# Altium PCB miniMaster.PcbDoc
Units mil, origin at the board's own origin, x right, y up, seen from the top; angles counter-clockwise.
Board outline 1394 x 785 mil, 4 copper layers (Top Layer, GND, VCC, Bottom Layer); 65 components, 42 nets, 262 pads, 110 vias.
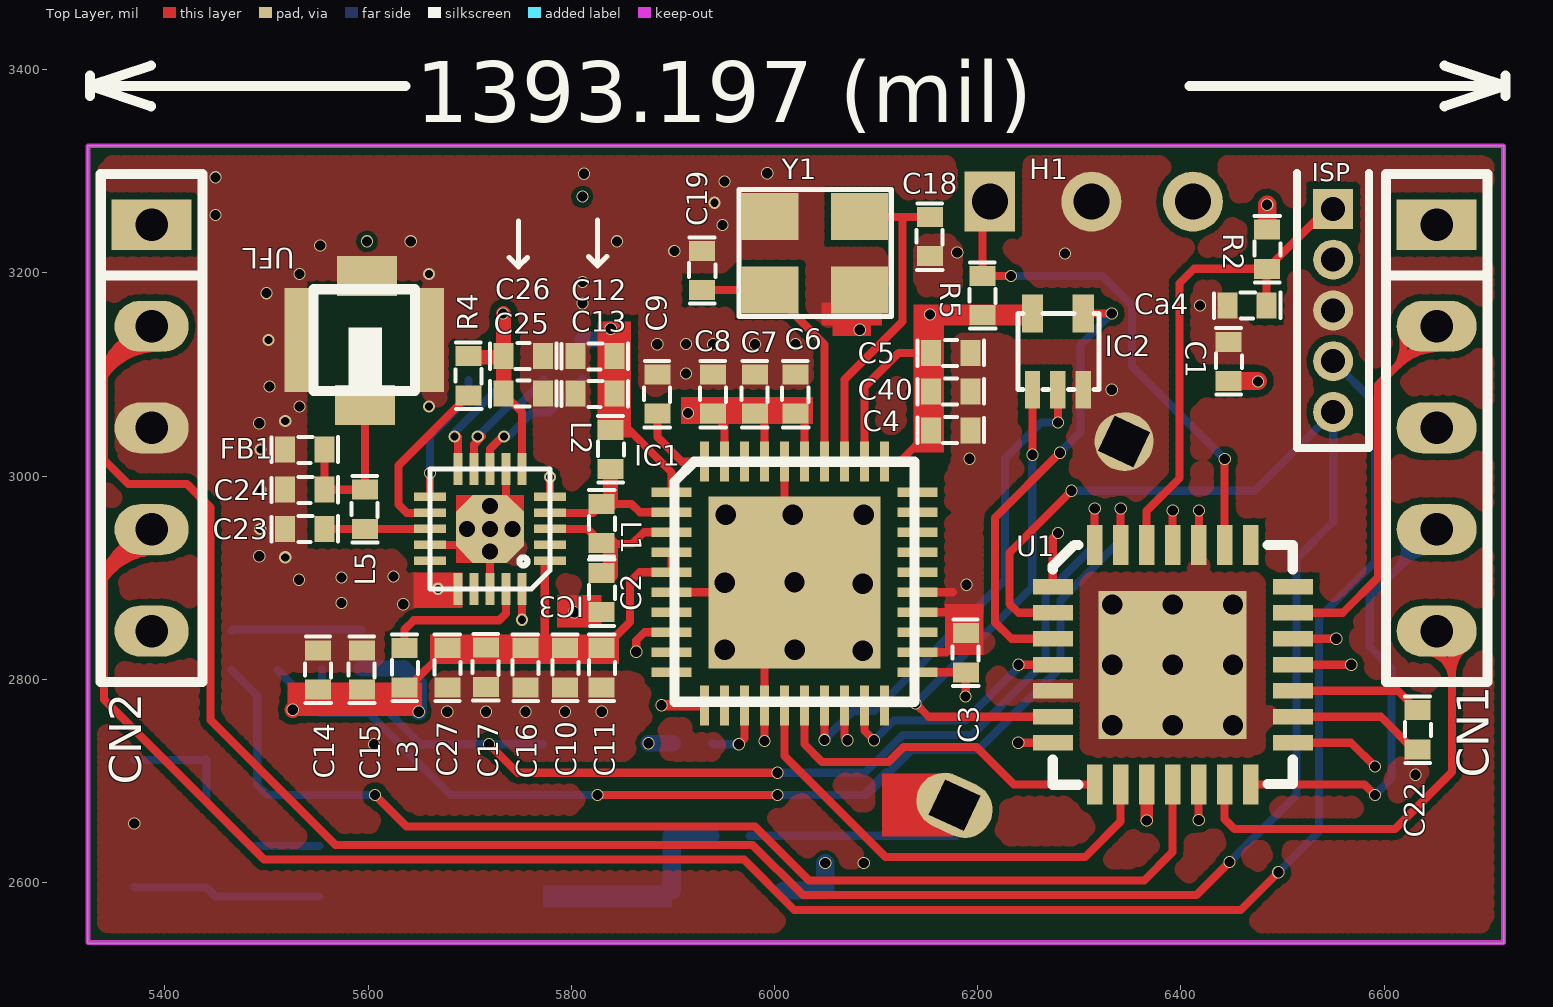
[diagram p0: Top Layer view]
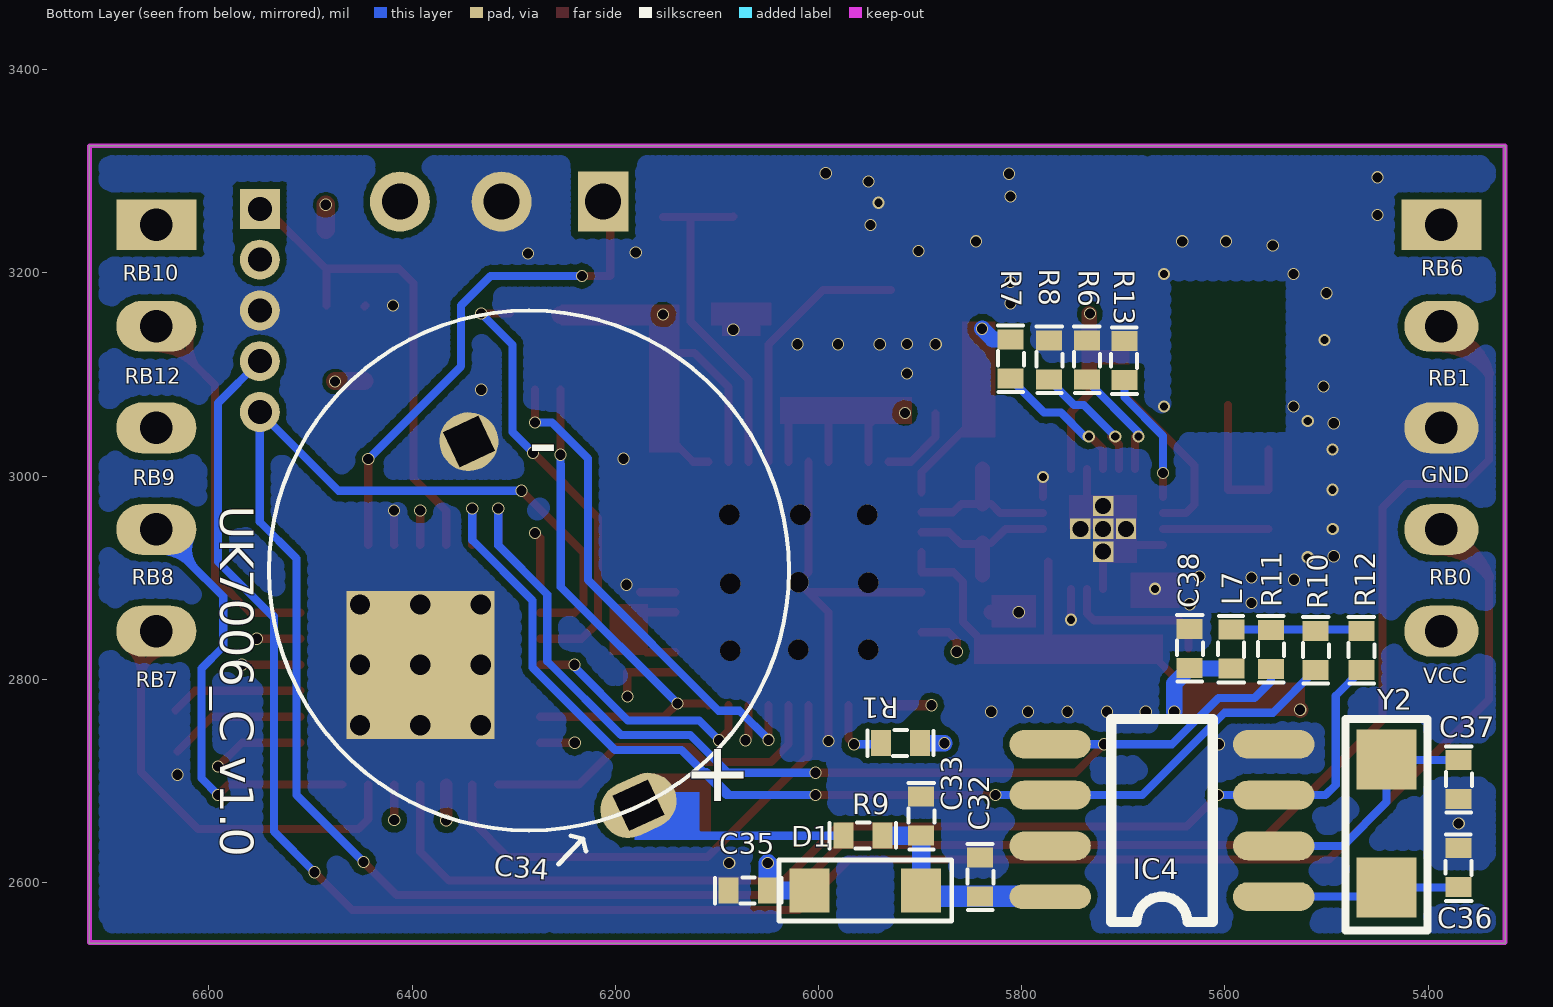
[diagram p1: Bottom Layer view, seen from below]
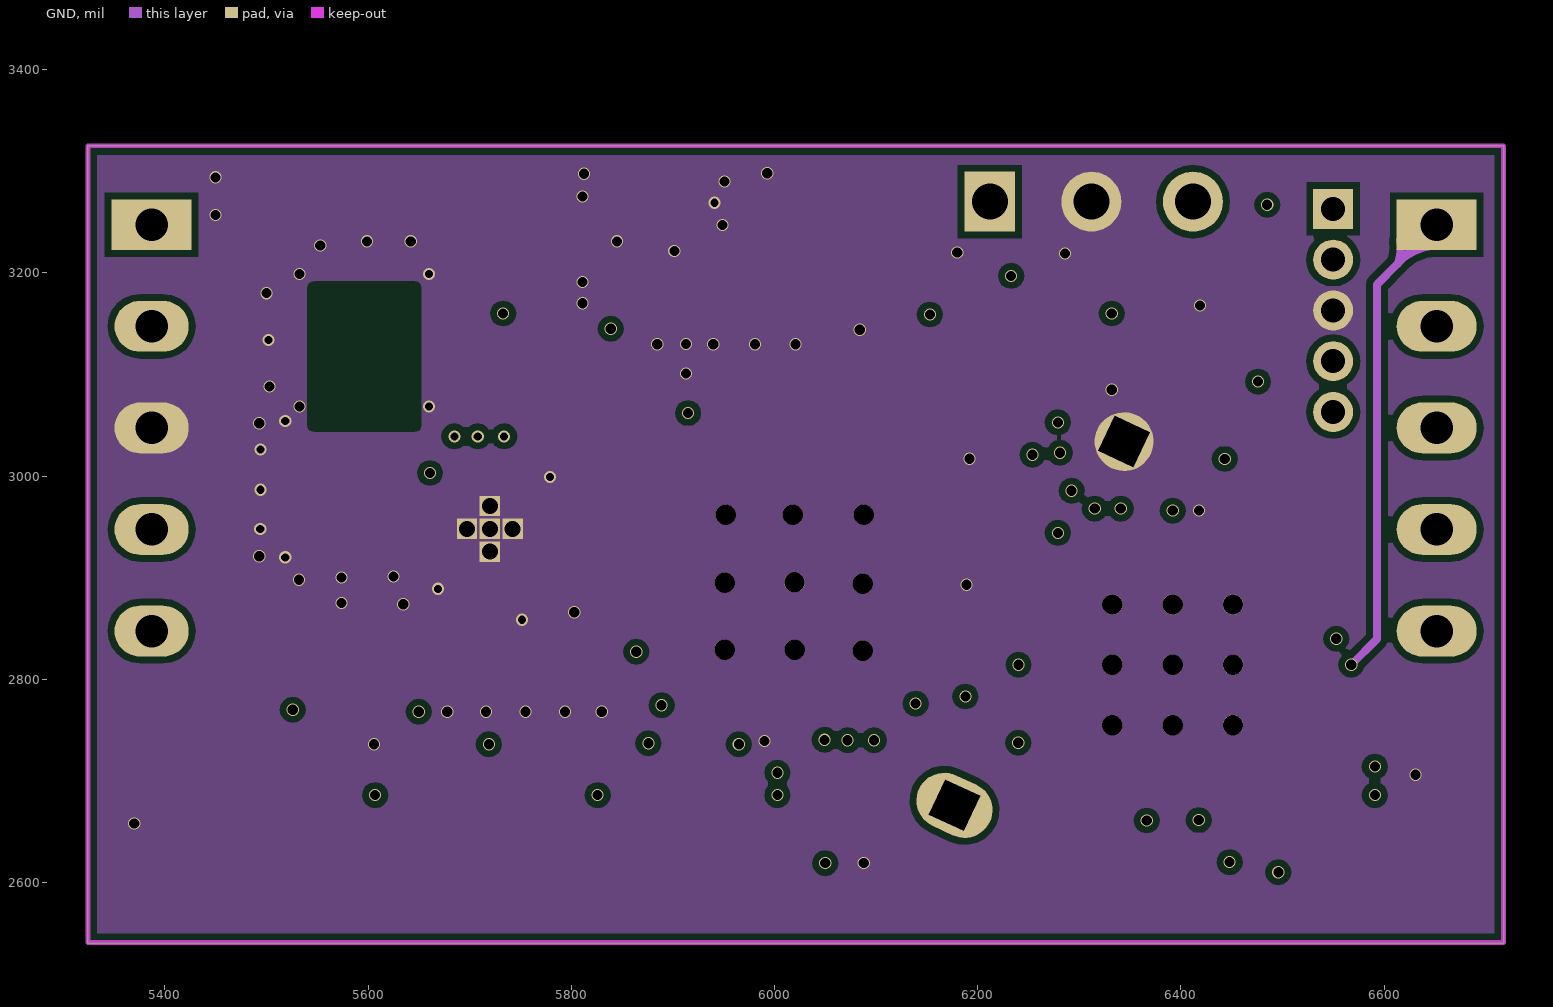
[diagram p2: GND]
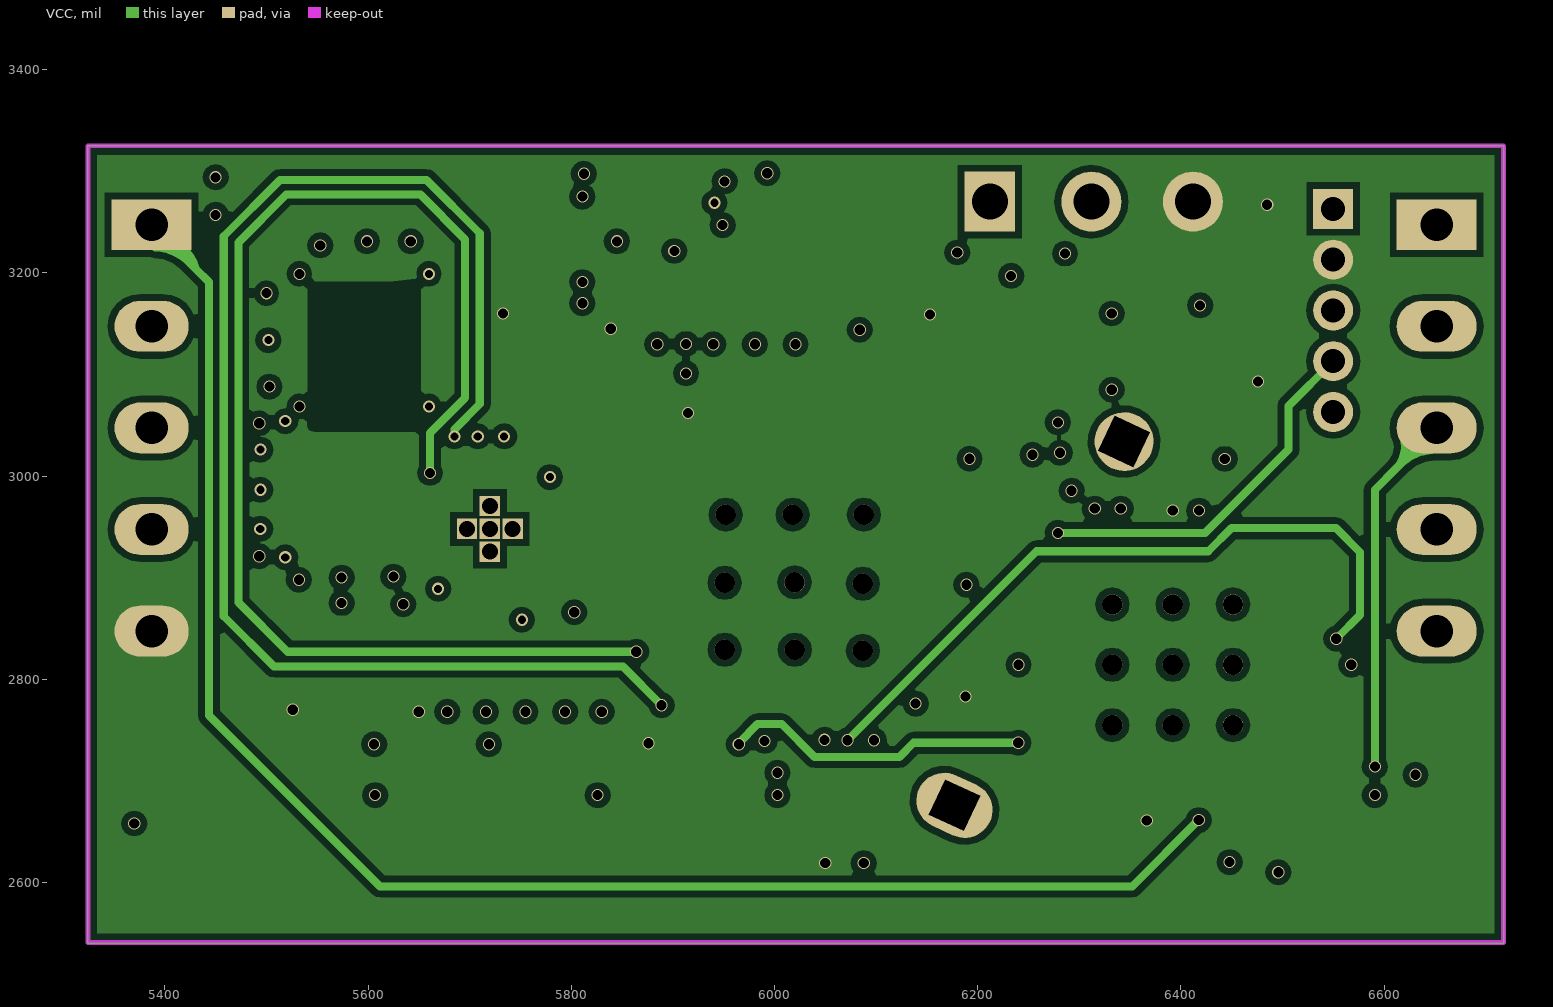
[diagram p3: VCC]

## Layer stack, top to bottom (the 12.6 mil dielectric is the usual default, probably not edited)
Top Layer: signal copper 1.4
Dielectric: core 12.6, FR-4, Dk 4.8
GND: signal copper 1.4
Dielectric: prepreg 12.6, FR-4, Dk 4.8
VCC: signal copper 1.4
Dielectric: core 12.6, FR-4, Dk 4.8
Bottom Layer: signal copper 1.4

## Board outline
5324,2540 5324,3325 6718,3325 6718,2540 5324,2540

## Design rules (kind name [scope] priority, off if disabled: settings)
Clearance [All] p1: gap=6.5
ComponentClearance [All] p1: gap=0 collisioncheckmode=3 verticalgap=0 showdistances=FALSE
HoleSize [All] p1: absolutevalues=TRUE maxlimit=1000 minlimit=1 maxpercent=80.000 minpercent=20.000
HoleToHoleClearance [All] p1: gap=0 allowstackedmicrovias=TRUE
MinimumSolderMaskSliver [All] p1: minsoldermaskwidth=0
PolygonConnect [All] p1: connectstyle=Direct reliefconductorwidth=10 reliefentries=4 polygonreliefangle="45 Angle"
RoutingVias [All] p1: holewidth=10 width=15 viastyle="Through Hole" minholewidth=8 minwidth=12 maxholewidth=18 maxwidth=100
SilkToSilkClearance [All] p1: silktosilkclearance=0
SilkscreenOverComponentPads [All] p1: minsilkscreentomaskgap=0
SolderMaskExpansion [All] p1: expansion=4
Width [All] p1: maxlimit=100 minlimit=8 preferedwidth=8
22 further rules are at their usual default settings.

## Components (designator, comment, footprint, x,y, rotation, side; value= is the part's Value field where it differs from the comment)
C1 "Cap" C0402 6447,3093.49 r90 top
C2 "Cap" C0402 5830,2866 r90 top
C3 "Cap" C0402 6188.35,2845.35 r270 top
C4 "Cap" C0402 6192.76,3045 r180 top
C5 "Cap" C0402 6192.76,3121 r180 top
C6 "Cap" C0402 6020.76,3100 r270 top
C7 "Cap" C0402 5980.76,3100 r270 top
C8 "Cap" C0402 5939.76,3100 r270 top
C9 "Cap" C0402 5884.76,3100 r270 top
C10 "Cap" C0402 5794,2792 r90 top
C11 "Cap" C0402 5830,2792 r90 top
C12 "Cap" C0402 5804,3118 r0 top
C13 "Cap" C0402 5804,3081 r0 top
C14 "Cap" C0402 5551,2828.51 r270 top
C15 "Cap" C0402 5594,2828.51 r270 top
C16 "Cap" C0402 5755,2792 r90 top
C17 "Cap" C0402 5716,2831 r270 top
C18 "Cap" C0402 6153,3255 r270 top
C19 "Cap" C0402 5928.76,3183 r90 top
C22 "Cap" C0402 6633,2731 r90 top
C23 "Cap" C0402 5518.49,2948.06 r0 top
C24 "Cap" C0402 5518.49,2986.57 r0 top
C25 "Cap" C0402 5772,3081 r180 top
C26 "Cap" C0402 5772,3118 r180 top
C27 "Cap" C0402 5678,2792 r90 top
C32 "Cap" C0402 5841,2586 r90 bottom
C33 "Cap" C0402 5899,2646 r90 bottom
C34 "Cap Pol1" 0.22f 6285,2907 r65 bottom
C35 "Cap" C0402 6050,2592 r0 bottom
C36 "Cap" C0402 5370,2634 r270 bottom
C37 "Cap" C0402 5370,2682 r90 bottom
C38 "Cap" C0402 5634.76,2811 r90 bottom
C40 "Cap" C0402 6192.76,3083 r180 top
Ca4 "Cap" C0402 6446,3168 r0 top
CN1 "CN1" SIP5#1 6651.87,3047.4 r270 top locked
CN2 "CN2" SIP5#2 5386.99,3047.4 r270 top locked
D1 "Diode 1N4148WS" sod323 6009,2592 r180 bottom
FB1 "Res1" C0402 5518.49,3026 r0 top
H1 "H1" HDR1X3 6212,3270 r0 top locked
IC1 "mrf24j40" mrf24j40 5898.76,2984 r0 top
IC2 "NC7SZ125P5X" NC7SZ125P5X 6254,3085 r0 top
IC3 "2438T" 2438T 5779,2889 r180 top locked
IC4 "pcf8563T" pcf8563t 5552,2586 r90 bottom
ISP "ISP" 1.27MM 6550,3263 r90 top locked
L1 "Inductor" c0402 5830,2934 r90 top
L2 "Inductor" c0402 5838.76,3007 r90 top
L3 "Inductor" c0402 5636,2792 r90 top
L5 "Inductor" c0402 5597,2986.57 r270 top
L7 "Inductor" c0402 5593.76,2849 r270 bottom
R1 "Res1" C0402 5900,2737 r0 bottom
R2 "Res1" C0402 6485,3204 r90 top
R4 "Res1" C0402 5699,3118 r270 top
R5 "Res2" C0402 6205,3197 r270 top
R6 "Res1" C0402 5736,3095 r90 bottom
R7 "Res1" C0402 5811,3096 r90 bottom
R8 "Res1" C0402 5773,3095 r90 bottom
R9 "Res1" C0402 5937,2646 r0 bottom
R10 "Res1" C0402 5510.76,2809 r90 bottom
R11 "Res1" C0402 5554.76,2810 r90 bottom
R12 "Res1" C0402 5465.76,2809 r90 bottom
R13 "Res1" C0402 5699,3133 r270 bottom
U1 "QFN256" QFN256 6274,2891 r0 top locked
UFL "IPEX" UFL 5597,3070 r270 top locked
Y1 "20MHz" 20mhz 5995.76,3183 r0 top
Y2 "32.768k" 32.768K 5441,2721 r270 bottom

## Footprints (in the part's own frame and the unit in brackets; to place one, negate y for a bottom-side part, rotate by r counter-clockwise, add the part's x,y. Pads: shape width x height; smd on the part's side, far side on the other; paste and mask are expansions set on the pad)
0.22f [mil]
  oval 55x77 hole 38 square: 1(-255,0)
  round 58 hole 38 square: 2(140,0)
  silkscreen extent -256,-256 256,256
1.27MM [mm]
  rect 1x1 hole 0.6: 1(0,0)
  round 1 hole 0.6: 2(-1.27,0) 3(-2.54,0) 4(-3.81,0) 5(-5.08,0)
  silkscreen extent -5.98,-0.9 0.9,0.9
20mhz [mil]
  rect 56x46 smd: 0(0,72.56) 0(88,0) 1(0,0) 2(88,72.56)
  silkscreen extent -31,-26 119,99
32.768K [mm]
  rect 1.5x1.5 smd: 1(0,0) 2(3.2,0)
  silkscreen extent -1.01,-1.02 4.27,1.03
2438T [mm]
  rect 0.508x0.508 hole 0.4: 0(0.93,-1.5) 0(1.5,-2.07) 0(1.5,-1.5) 0(1.5,-0.93) 0(2.07,-1.5)
  oct 1.7x1.7 smd: 0(1.5,-1.5)
  rect 0.8x0.22 smd: 1(0,-0.7) 2(0,-1.1) 3(0,-1.5) 4(0,-1.9) 5(0,-2.3) 11(3,-2.3) 12(3,-1.9) 13(3,-1.5) 14(3,-1.1) 15(3,-0.7)
  rect 0.22x0.8 smd: 6(0.7,-3) 7(1.1,-3) 8(1.5,-3) 9(1.9,-3) 10(2.3,-3) 16(2.3,0) 17(1.9,0) 18(1.5,0) 19(1.1,0) 20(0.7,0)
  Top Layer region: 1.5,-2.35 2.35,-2.35 2.35,-0.65 1.5,-0.65
  Top Layer region: 0.65,-2.35 2.35,-2.35 2.35,-1.5 0.65,-1.5
  silkscreen extent 0,-3 3,0
C0402 [mm]
  rect 0.5x0.65 smd: 1(0,0) 2(0.978,0)
  silkscreen extent -0.34,-0.33 1.32,0.32
c0402 [mm]
  rect 0.5x0.65 smd: 1(0,0) 2(0.978,0)
  silkscreen extent -0.34,-0.33 1.32,0.32
HDR1X3 [mm] "Connector; Header; 3 Position"
  rect 1.27x1.5 hole 0.9: 1(0,0)
  round 1.5 hole 0.9: 2(2.54,0) 3(5.08,0)
mrf24j40 [mm]
  rect 1x0.23 smd: 1(0,0) 2(0,-0.5) 3(0,-1) 4(0,-1.5) 5(0,-2) 6(0,-2.5) 7(0,-3) 8(0,-3.5) 9(0,-4) 10(0,-4.5) 21(6.15,-4.5) 22(6.15,-4) 23(6.15,-3.5) 24(6.15,-3) 25(6.15,-2.5) 26(6.15,-2) 27(6.15,-1.5) 28(6.15,-1) 29(6.15,-0.5) 30(6.15,0)
  round 0.508 hole 0.508: 10(1.327,-3.937) 10(1.327,-2.261) 10(1.352,-0.559) 10(3.029,-0.559) 10(3.075,-2.25) 10(3.079,-3.937) 10(4.781,-3.962) 10(4.781,-2.286) 10(4.807,-0.559)
  rect 0.23x1 smd: 11(0.825,-5.325) 12(1.325,-5.325) 13(1.825,-5.325) 14(2.325,-5.325) 15(2.825,-5.325) 16(3.325,-5.325) 17(3.825,-5.325) 18(4.325,-5.325) 19(4.825,-5.325) 20(5.325,-5.325) 31(5.325,0.765) 32(4.825,0.765) 33(4.325,0.765) 34(3.825,0.765) 35(3.325,0.765) 36(2.825,0.765) 37(2.325,0.765) 38(1.825,0.765) 39(1.325,0.765) 40(0.825,0.765)
  rect 4.3x4.3 smd: 41(3.075,-2.25)
  silkscreen extent 0.07,-5.24 6.07,0.76
NC7SZ125P5X [mil]
  rect 15x37 smd: 1(0,0) 2(25,0) 3(50,0)
  rect 21x37 smd: 4(50,75) 5(0,75)
  silkscreen extent -14,0 66,75
pcf8563t [mil]
  oval 28.35x80 smd: 1(0,0) 2(50,0) 3(100,0) 4(150,0) 5(150,220) 6(100,220) 7(50,220)
  oval 24x80 smd: 8(0,220)
  silkscreen extent -25,60 175,160
QFN256 [mm]
  rect 3.7x3.7 smd: 0(2.997,-1.95)
  rect 1x0.38 smd: 1(0,0) 2(0,-0.65) 3(0,-1.3) 4(0,-1.95) 5(0,-2.6) 6(0,-3.25) 7(0,-3.9) 15(6,-3.9) 16(6,-3.25) 17(6,-2.6) 18(6,-1.95) 19(6,-1.3) 20(6,-0.65) 21(6,0)
  rect 0.38x1 smd: 8(1.047,-4.947) 9(1.697,-4.947) 10(2.347,-4.947) 11(2.997,-4.947) 12(3.647,-4.947) 13(4.297,-4.947) 14(4.947,-4.947) 22(4.947,1.047) 23(4.297,1.047) 24(3.647,1.047) 25(2.997,1.047) 26(2.347,1.047) 27(1.697,1.047) 28(1.047,1.047)
  silkscreen extent 0,-4.95 6,1.05
SIP5#1 [mil]
  rect 50x78.74 hole 32: 1(-200,0)
  oval 50x78.74 hole 32: 2(-100,0) 3(0,0) 4(100,0) 5(200,0)
  silkscreen extent -250,-50 250,50
SIP5#2 [mil]
  rect 50x78.74 hole 32: 1(-200,0)
  oval 50x73 hole 32: 2(-100,0) 3(0,0) 4(100,0) 5(200,0)
  silkscreen extent -250,-50 250,50
sod323 [mm]
  rect 1x1.1 smd: 1(0,0) 2(2.794,0)
  silkscreen extent -0.76,-0.76 3.56,0.76
UFL [mm]
  rect 1x1.5 smd: 1(0,0) 3(-3.22,0.05)
  rect 2.6x0.75 smd: 2(-1.62,1.6) 4(-1.62,-1.64)
  silkscreen extent -2.89,-1.29 -0.35,1.25

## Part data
C1 C2 C3 C4 C5 C6 C7 C8 C9 C10 C11 C12 C13 C14 C15 C16 C17 C18 C19 C22 C23 C24 C25 C26 C27 C32 C33 C35 C36 C37 C38 C40 Ca4: "Capacitor"
C34: "Polarized Capacitor (Radial)"
CN1 CN2 ISP: library part CON5, "Connector"
D1: library part "Diode 1N4148", "High Conductance Fast Diode"
FB1 R1 R2 R4 R5 R6 R7 R8 R9 R10 R11 R12 R13: "Resistor"
H1: library part "Header 3", "Header, 3-Pin"
UFL: library part "Header 4", "Hea"
Y1 Y2: library part XTAL, "Crystal Oscillator"

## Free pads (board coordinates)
  rect 145.67x145.67 smd far side: 0(6392,2814.23)
  round 20 hole 20: 1(6332.64,2754.87) 1(6332.64,2814.23) 1(6332.64,2873.59) 1(6392,2754.87) 1(6392,2814.23) 1(6392,2873.59) 1(6451.36,2754.87) 1(6451.36,2814.23) 1(6451.36,2873.59)

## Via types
v1: diameter 12, hole 10, Top Layer to Bottom Layer, 95 vias
v2: diameter 12, hole 8, Top Layer to Bottom Layer, 15 vias

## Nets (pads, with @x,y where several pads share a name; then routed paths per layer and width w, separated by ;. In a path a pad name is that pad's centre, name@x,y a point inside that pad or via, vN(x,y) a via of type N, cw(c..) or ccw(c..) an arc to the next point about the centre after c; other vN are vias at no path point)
C\S\: IC1.20 IC2.1 U1.6 | length 648.7
  Top Layer w8: IC1.20 6110.06,2776 v1(6139,2776) 6151.95,2763.05 U1.6 ; v1(6254,3021) IC2.1
  Bottom Layer w8: v1(6139,2776) 6253.76,2890.76 ; 6253.76,3011.24 6253.76,2890.76 ; v1(6254,3021) 6254,2891 6253.76,2890.76
CPS: IC3.8 R7.1 | length 139.5
  Top Layer w8: IC3.8 5719.94,3026.44 5732.51,3039 v2(5734,3039)
  Bottom Layer w8: v2(5734,3039) 5737.99,3039 5761.5,3062.5 5777.99,3062.5 5811,3095.51 R7.1
CRX: IC1.11 IC3.10 R6.1 | length 1499.8
  Top Layer w8: v2@5688,3039 5688.45,3038.55 IC3.10
  Top Layer w10: v1(5889,2774.35) IC1.11
  VCC w8: v2(5685,3039) 5685,3046 5710,3071 5710,3239 5657.5,3291.5 5513.49,3291.5 5458,3236.01 5458,2862 5507.5,2812.5 5850.85,2812.5 v1(5889,2774.35)
  Bottom Layer w8: v2(5685,3039) 5685,3043 5736,3094 R6.1
CSD: IC3.12 R4.2 | length 170.4
  Top Layer w8: IC3.12 5638.2,2963.8 5630,2972 5630,3010.49 R4.2
CTX: IC1.8 IC3.11 R13.2 | length 1447
  Top Layer w8: IC3.11 5660.89,2998.89 v1@5661,2999 ; v1(5864,2827) 5864,2838 5872.2,2846.2 IC1.8
  VCC w8: v1(5661,3003) 5661,3042.51 5695.5,3077.01 5695.5,3232.99 5651.49,3277 5519.5,3277 5472.5,3230 5472.5,2875.5 5521,2827 v1(5864,2827)
  Bottom Layer w8: v1(5661,3003) 5661,3039.51 5699,3077.51 R13.2
GND: C1.2 C2.1 C3.1 C4.1 C5.1 C6.1 C7.1 C8.1 C9.1 C10.1 C11.1 C12.1 C13.1 C14.1 C15.1 C16.1 C17.2 C18.2 C19.2 C22.1 C23.1 C24.1 C25.1 C26.1 C27.1 C32.2 C33.2 C34.2 C35.2 C36.1 C37.1 C38.2 C40.1 Ca4.1 CN2.3 FB1.1 H1.2 IC1.6 IC1.10@5951,2829 IC1.10@5951,2895 IC1.10@5952,2962 IC1.10@6018,2962 IC1.10@6019.83,2895.42 IC1.10@6020,2829 IC1.10@6087,2828 IC1.10@6087,2894 IC1.10@6088,2962 IC1.14 IC1.22 IC1.24 IC1.25 IC1.36 IC1.41 IC2.3 IC3.0 IC3.5 IC3.7 IC3.14 IC3.16 IC3.18 IC3.20 IC4.4 ISP.3 pad.0 pad.1 R6.2 R8.2 R13.1 U1.0 U1.5 U1.16 U1.24 UFL.2 UFL.3 UFL.4 Y1.0 | length 1020
  Top Layer w8: IC3.14 5704.2,2932.31 IC3.0@5719.94,2948.06 ; v2(5669,2889) IC3.16 ; IC3.18 5719.94,2925.61 IC3.0@5719.94,2948.06 ; IC3.7 5735.69,2963.8 5731.17,2959.28 IC3.0@5719.94,2948.06 ; v2(5751.44,2858.56) IC3.20 ; IC3.5 v2(5779,2999) ; v1@5810.54,3274.54 v1(5811,3275) ; IC1.6 IC1.41@6009.98,2885.57 ; v1(5990.3,2739.3) IC1.14 5990.3,2865.89 IC1.41@6009.98,2885.57 ; IC1.36 6009.98,2905.26 IC1.41 IC1.41@6009.98,2885.57 ; IC1.22 6169.52,2826.52 C3.1 ; IC1.24 6174.92,2865.89 ; IC1.25 6175.6,2885.57 ; U1.0@6366.41,2788.64 U1.0 ; U1.24 6418,2932.64 v1(6418,2966) ; Ca4.1 Ca4.1@6447,3167 ; U1.16 6596.95,2763.05 C22.1@6631,2729
  Top Layer w15: v1(5803,2866) C2.1
  other v1: 6088,2619 5370,2658 6631,2706 5606,2736 5678,2768 5716,2768 5755,2768 5794,2768 5830,2768 5634.76,2873.76 5574,2875 6189,2893 5532,2898 5574,2900 5625,2901 5493,2921 6192,3017 5493,3052 5532.43,3068.57 6332,3085 5503,3088 5913,3101 5884.76,3129.76 5913,3130 5939.76,3129.76 5980.76,3129.76 6020.76,3129.76 6084,3144 6419,3168 5811,3170 5500,3180 5811,3191 5532.43,3198.99 6286,3219 6180,3220 5901.51,3221.51 5553,3227 5599,3231 5642,3231 5845,3231 5949,3247 5450,3257 5951,3290 5450,3294 5812.52,3297.57 5993,3298
  other v2: 5518.49,2920 5494,2948 5494.06,2986.57 5494.06,3026 5518.49,3054.06 5659.99,3068.57 5502,3133.78 5659.99,3198.99 5941,3269
INT: IC1.16 U1.8 | length 352.5
  Top Layer w8: IC1.16 6029.67,2736 6047,2718.67 6112.43,2718.67 6127,2733.23 6167.12,2733.23 6198.77,2733.23 6235.77,2696.23 U1.8
INT_T: IC4.3 R12.1 U1.11 | length 1141.2
  Top Layer w8: v1(5607,2686) 5638,2655 5981,2655 6034,2602 6364,2602 6392,2630 U1.11
  Bottom Layer w8: R12.1 5491,2783.76 5491,2696 5501,2686 IC4.3 v1(5607,2686)
ISPCLK: CN2.2 ISP.5 U1.2 | length 2636.4
  Top Layer w8: CN2.2 5339.99,3100.4 5339.99,3016.01 5364,2992 5422,2992 5445,2969 5445,2760 5568,2637 5978.49,2637 6027.99,2587.5 6415.5,2587.5 v1(6448,2620) ; U1.2 6240.09,2865.41 6231.5,2874 6231.5,2924.48 v1(6292.51,2985.49)
  Top Layer w10: CN2.2@5365.3,3135.53 ccw(c5397,3086) 5339.99,3100.4 cw(c5393,3061) CN2.2@5393.64,3127.05
  Bottom Layer w8: v1(6292.51,2985.49) 6472.49,2985.49 ISP.5 6550,2955 6514,2919 6514,2686 v1(6448,2620)
ISPDAT: CN2.4 ISP.4 U1.1 | length 2558.7
  Top Layer w8: CN2.4 5339.99,2900.4 5339.99,2780.01 5497.5,2622.5 5970,2622.5 6019.5,2573 6459,2573 v1(6496,2610) ; U1.1 6274,2939 v1(6279,2944)
  Top Layer w10: CN2.4@5387.94,2942.13 ccw(c5399,2881) 5339.99,2900.4 cw(c5393,2861) CN2.4@5394.74,2927.03
  VCC w8: v1(6279,2944) 6424,2944 6506,3026 6506,3069 ISP.4 ISP.4@6550,3109.67
  Bottom Layer w8: v1(6496,2610) 6536,2650 6536,2862 6537.33,2862 6591,2915.67 6591,3072 ISP.4
MCLR: Ca4.2 ISP.1 R2.1 U1.26 | length 488.7
  Top Layer w8: U1.26 6366.41,2965.41 6398.78,2997.78 6398.78,3189.78 6413,3204 R2.1 ; Ca4.2 6484.51,3203.51 R2.1 ; ISP.1 6544,3263 R2.1
NetC9_2: C9.2 IC1.40 | length 79.7
  Top Layer w8: C9.2 5884.76,3038.24 5908.88,3014.12 IC1.40
NetC18_1: C18.1 IC1.33 Y1.2 | length 333.9
  Top Layer w8: IC1.33 6069.04,3095.04 6126,3152 6126,3255 ; Y1.2 6084.33,3255 6126,3255 ; C18.1 6126,3255
NetC19_1: C19.1 IC1.34 Y1.1 | length 258.1
  Top Layer w8: C19.1 Y1.1 6049.35,3129.41 IC1.34
NetC22_2: C22.2 U1.17 | length 130.7
  Top Layer w8: U1.17 6613.87,2788.64 C22.2
NetC24_2: C24.2 FB1.2 L5.1 UFL.1 | length 162.9
  Top Layer w8: FB1.2 C24.2 L5.1 UFL.1
NetC32_1: C32.1 C33.1 D1.2 IC4.8 R9.1 | length 92
  Bottom Layer w18: D1.2 C33.1 R9.1
NetC34_1: C34.1 R9.2 | length 171.8
  Bottom Layer w8: R9.2 6117.34,2646 6138.5,2667.16
NetC36_2: C36.2 IC4.1 Y2.2 | length 185.9
  Bottom Layer w8: C36.2 5370.47,2595.02 Y2.2 5450.02,2586 IC4.1
NetC37_2: C37.2 IC4.2 Y2.1 | length 242
  Bottom Layer w8: C37.2 5440.51,2720.51 Y2.1 5441,2679 5484,2636 IC4.2
NetIC1_17: IC1.17 IC2.2 | length 495.7
  Top Layer w8: v1(6049.35,2740.36) IC1.17 ; v1(6279,3052.76) IC2.2
  Bottom Layer w8: v1(6049.35,2740.36) 6049.35,2740.69 6077.67,2769 6098.5,2769 6227,2897.5 6227,3017.33 6262.43,3052.76 v1(6279,3052.76)
NetIC3_9: IC3.9 R8.1 | length 123.6
  Top Layer w8: IC3.9 5704.2,3031.2 v2@5712,3039
  Bottom Layer w8: v2(5708,3039) 5739,3070 5748.49,3070 5773,3094.51 R8.1
NetIC3_19: IC3.19 L3.2 | length 149
  Top Layer w8: L3.2 5636,2849 5645,2858 5729,2858 5735.69,2864.69 IC3.19
NetL7_1: L7.1 R10.2 R11.2 R12.2 | length 128.6
  Bottom Layer w8: R12.2 5467.25,2849 L7.1
R\E\S\E\T\: IC1.13 R1.2 U1.7 | length 404.7
  Top Layer w8: v1(5965,2736) 5970.61,2741.61 IC1.13 ; v1(6240,2737.46) U1.7
  VCC w8: v1(5965,2736) 5965,2737.33 5983.47,2755.8 6007.2,2755.8 6039.5,2723.5 6123.04,2723.5 6137,2737.46 v1(6240,2737.46)
  Bottom Layer w8: R1.2 5939.51,2736 v1(5965,2736)
RB6: CN2.1 U1.12 | length 1686.1
  Top Layer w8: v1(6417.59,2661.41) U1.12
  VCC w8: CN2.1 5421,3213.39 ; CN2.1@5390.64,3225.18 cw(c5389,3176) 5421,3213.39 ; CN2.1@5403.88,3233.09 cw(c5388,3192) 5430.39,3204 ; v1(6417.59,2661.41) 6352.18,2596 5611.99,2596 5443.5,2764.49 5443.5,3190.89 5430.39,3204 ; 5421,3213.39 5430.39,3204
RB7: CN1.5 U1.13 | length 505.8
  Top Layer w8: U1.13 6443.18,2662.32 6453,2652.5 6610.64,2652.5 6667,2708.86 6667,2804 ; CN1.5@6637.86,2827.42 cw(c6639,2799) 6667,2804 ; CN1.5 6667,2832.27 6667,2808 ; CN1.5@6682.5,2833.49 ccw(c6699,2806) 6667,2808 ; 6667,2804 cw(c6699,2806) 6667,2808 ; 6667,2804 6667,2808
RB8: CN1.4 U1.14 | length 506
  Top Layer w8: U1.14 6580.77,2696.23 v1(6591,2686)
  Bottom Layer w8: v1(6591,2686) 6607.5,2702.5 6607.5,2810.5 6586,2832 6586,2881.53 6621,2916.53 ; CN1.4@6617.8,2940.51 cw(c6591,2928) 6614.47,2910 cw(c6650,2881) 6621,2916.53 ; CN1.4 6621,2916.53 ; CN1.4@6652.18,2926.81 ccw(c6650,2881) 6621,2916.53
RB9: CN1.3 U1.15 | length 526.9
  Top Layer w8: U1.15 6567.54,2737.46 v1(6591,2714)
  VCC w8: v1(6591,2714) 6591,2986.53 6612.47,3008 ; CN1.3@6616.89,3043.94 cw(c6590,3029) 6613.53,3009.19 ; CN1.3@6646.24,3025.82 ccw(c6652,2974) 6618,3013.53 ; CN1.3 6618,3013.53 ; 6612.47,3008 cw(c6652,2974) 6613.53,3009.19 ; 6612.47,3008 ccw(c6590,3029) 6613.53,3009.19 ; 6612.47,3008 6618,3013.53 ; 6613.53,3009.19 cw(c6652,2974) 6618,3013.53
RB10: CN1.1 U1.18 | length 589.8
  Top Layer w8: U1.18 v1(6567.77,2814.23)
  GND w8: v1(6567.77,2814.23) 6593,2839.46 6593,3188.53 6613.47,3209 ; CN1.1@6615.95,3232.34 cw(c6574,3225) 6613.47,3209 ; CN1.1 6619.47,3215 ; CN1.1@6657.29,3226.57 ccw(c6653,3173) 6619.47,3215 ; 6613.47,3209 6619.47,3215
RB12: CN1.2 U1.20 | length 443.3
  Top Layer w8: U1.20 6559.41,2865.41 6594,2900 6594,3089.53 6614,3109.53 ; CN1.2@6617.73,3139.92 cw(c6581,3129) 6614,3109.53 ; CN1.2 6614,3109.53 ; CN1.2@6651.93,3125.91 ccw(c6654,3069) 6614,3109.53
RB15: H1.1 R5.1 U1.23 | length 505.6
  Top Layer w8: H1.1@6205,3270 R5.1 v1(6233,3197) ; U1.23 v1(6443.18,3016.82)
  Bottom Layer w8: v1(6233,3197) 6323,3197 6352,3168 6352,3108 v1(6443.18,3016.82)
SCK: IC1.19 U1.4 | length 246.3
  Top Layer w8: IC1.19 6088.73,2749.27 v1(6098,2740) ; v1(6240.23,2814.23) U1.4
  Bottom Layer w8: v1(6098,2740) 6117.5,2759.5 6187.83,2759.5 6240.23,2811.89 v1(6240.23,2814.23)
SCK_T: IC4.6 R10.1 U1.27 | length 1122.3
  Top Layer w8: v1(5826,2686) v1(6003,2686) ; U1.27 v1(6340.82,2968)
  Bottom Layer w8: R10.1 5552.76,2767 5600.46,2767 5681.46,2686 IC4.6 v1(5826,2686) ; v1(6003,2686) 6087.84,2686 ; 6110.42,2708.58 6087.84,2686 ; v1(6340.82,2968) 6340.82,2936.81 6281.51,2877.49 6281.51,2811.67 6200.34,2730.5 6135,2730.5 6090.5,2686 6087.84,2686
SDA_T: IC4.5 R11.1 U1.28 | length 1066.2
  Top Layer w8: v1(5719,2736) 5747,2708 v1(6003,2708) ; U1.28 v1(6315.23,2968)
  Bottom Layer w8: R11.1 5554.76,2797.74 5571,2781.5 5606.46,2781.5 5651.96,2736 v1(5719,2736) IC4.5 ; v1(6003,2708) 6089.33,2708 6126.33,2745 6194.33,2745 6267.01,2817.67 6267.01,2883.5 6315.23,2931.72 v1(6315.23,2968)
SDI: IC1.18 U1.19 | length 774.1
  Top Layer w8: IC1.18@6069,2774.31 IC1.18 6069.04,2742.96 v1(6072,2740) ; U1.19 v1(6553,2839.82)
  VCC w8: v1(6072,2740) 6258,2926 6427,2926 6449.73,2948.73 6552.77,2948.73 6576.5,2925 6576.5,2863.32 v1(6553,2839.82)
SDO: IC2.4 U1.3 | length 443.3
  Top Layer w8: U1.3 6233.18,2839.82 6217,2856 6217,2959 v1(6281,3023) ; IC2.4 v1(6332,3160)
  Bottom Layer w8: v1(6281,3023) 6301.22,3043.22 6301.22,3129.22 v1(6332,3160)
SMA: C23.2 IC3.13 L5.2 | length 103.9
  Top Layer w8: C23.2 L5.2 IC3.13
TRXN: C2.2 IC1.3 IC3.3 L1.1 | length 153.5
  Top Layer w8: IC3.3 5815.94,2948.06 L1.1 ; L1.1@5838.76,2934 5839.76,2933 5860,2933 5871.63,2944.63 IC1.3
  Top Layer w15: C2.2@5838.76,2902.51 L1.1@5838.76,2934
TRXP: IC1.2 IC3.4 L1.2 L2.1 | length 152.5
  Top Layer w8: IC3.4 5821.29,2963.8 L1.2 ; L1.2@5838.76,2972.51 5859.49,2972.51 5867.68,2964.32 IC1.2
  Top Layer w15: L1.2@5838.76,2972.51 L2.1
VCC: C1.1 C3.2 C4.2 C5.2 C6.2 C7.2 C8.2 C10.2 C11.2 C12.2 C13.2 C14.2 C15.2 C16.2 C17.1 C25.2 C26.2 C27.2 C35.1 C38.1 C40.2 CN2.5 D1.1 H1.3 IC1.1 IC1.4 IC1.5 IC1.21 IC1.31 IC1.32 IC1.35 IC1.37 IC1.39 IC2.5 IC3.1 IC3.6 ISP.2 L2.2 L3.1 L7.2 R1.1 R2.2 R4.1 R5.2 R7.2 U1.10 U1.25 | length 1672.1
  Top Layer w8: C14.2 C15.2 5634,2790 L3.1 5639.49,2792 C27.2 ; R4.1 C26.2 C25.2 5751.44,3063.05 IC3.6 ; C16.2 C10.2 C11.2 ; 5774,2831 IC3.1@5774,2916.05 ; C11.2@5830,2828.51 5858,2856.51 5858,2896 5867.26,2905.26 IC1.5 IC1.4 ; L2.2 5856.98,3045.51 5898.76,3003.73 IC1.1 ; C8.2 5950.93,3050.32 IC1.39 ; C7.2 5990.3,3051.95 IC1.37 ; C6.2 6029.67,3052.58 IC1.35 ; IC1.32 6088.72,3087.72 6122,3121 C5.2 ; IC1.31 6123.37,3014.12 C4.2 ; IC1.21 C3.2 6188.35,2783.35 v1(6188,2783) ; U1.25 v1(6392,2966)
  Top Layer w12: v1(6366.41,2661) U1.10
  Top Layer w15: C26.2 v1@5733.49,3160 ; C4.2 C40.2 C5.2
  Top Layer w16: v1(5526,2770) 5546,2790 C14.2
  Top Layer w18: R5.2 IC2.5@6254,3158.49 ; C1.1 v1@6476,3093.49 ; R2.2 v1(6485,3267)
  Bottom Layer w16: L7.2 5634.25,2810.49 C38.1 5650,2795.76 v1(5650,2768) ; R7.2 5828.51,3134.51 v1(5839,3145) ; v1(5876,2737) R1.1
  Bottom Layer w18: D1.1 C35.1 v1(6050,2619)
  other v1: 5915,3062 6476,3093 6153,3159 5733,3160
WAKE: IC1.15 U1.9 | length 472.8
  Top Layer w8: IC1.15 6009.99,2724.35 6109.33,2625 6306,2625 6340.82,2659.82 U1.9
pads on no net: IC1.7 IC1.9 IC1.10@5898.76,2806.83 IC1.12 IC1.23 IC1.26 IC1.27 IC1.28 IC1.29 IC1.30 IC1.38 IC3.2 IC3.15 IC3.17 IC4.7 U1.21 U1.22

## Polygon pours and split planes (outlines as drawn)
VCC on VCC "BottomLayer-No Net" (solid, pour order 2): 5324,3325 5324,2540.8 6717.7,2540.8 6717.7,3325
GND on GND "BottomLayer-No Net" (solid, pour order 4): 5324.5,3325 5324.5,2540.8 6717.7,2540.8 6717.7,3325
GND on Top Layer "BottomLayer-No Net" (hatched 45Degree grid 8 track 20, pour order 6): 5324.5,3325 6717.7,3325 6717.7,2540.8 5324.5,2540.8
GND on Bottom Layer "BottomLayer-No Net" (hatched 45Degree grid 8 track 20, pour order 5): 5324.5,3325 6717.7,3325 6717.7,2540.8 5324.5,2540.8

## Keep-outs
Keep-Out Layer:
  lines w4.72: 5324.5,2540.8 6717.7,2540.8 6717.7,3325 5324.5,3325 5324.5,2540.8

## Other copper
Top Layer:
  rectangle net GND: 6046.38,3148 6106,3171
  rectangle net VCC: 5661,2815 5847,2844
  rectangle net VCC: 5521,2764 5653,2797
  rectangle net VCC: 6159,3148 6254,3169
  rectangle net VCC: 5908,3051 6038,3078
  rectangle net VCC: 5826,3038 5859,3152
  rectangle net VCC: 6137,3023 6167,3169
  region net NetC34_1: 6176,2707 6106,2707 6106,2645 6176,2645
  rectangle net VCC: 5726,3085 5741,3122
  rectangle net VCC: 5694,3110 5740,3124
  rectangle net GND: 6168,2824 6206,2874.02
  rectangle net GND: 6057,3138 6095,3154.26
  rectangle net GND: 5644.96,2870 5693,2905
  rectangle net GND: 5786,2851 5830,2883
Bottom Layer:
  rectangle net NetC34_1: 6117,2642 6181,2689
  rectangle net NetC32_1: 5772,2576 5899,2597

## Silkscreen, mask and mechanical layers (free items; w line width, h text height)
Top Overlay:
  circle w6: c5753,2916 r4
  rectangle: 5581,3088 5614,3146
  lines w5: 5748,3251 5748,3206 ; 5757,3215 5748,3206 ; 5826,3252 5826,3207 ; 5835,3216 5826,3207 ; 5748,3206 5739,3215 5748,3206 ; 5826,3207 5817,3216 5826,3207
  lines w10: 5326.28,3373.99 5326.28,3393.99 ; 5386.28,3363.99 5326.28,3383.99 ; 5386.28,3403.99 5326.28,3383.99 ; 5637,3383.99 5326.28,3383.99 ; 6408.76,3383.99 6719.48,3383.99 ; 6659.48,3363.99 6719.48,3383.99 ; 6659.48,3403.99 6719.48,3383.99 ; 6719.48,3373.99 6719.48,3393.99
  text "1393.197 (mil)" at 5647,3348 h60
Bottom Overlay:
  lines w4.72: 6229,2631 6232,2643 ; 6244,2646 6232,2643 ; 6256,2618 6232,2643
  text "RB6" at 5407,3197 h15
  text "RB10" at 6685,3192 h15
  text "RB12" at 6683,3091 h15
  text "RB1" at 5400,3089 h15
  text "-" at 6256,3005 h60
  text "GND" at 5407,2994 h15
  text "RB9" at 6675,2991 h15
  text "UK7006_C v1.0" at 6589,2971 h33 r90
  text "RB0" at 5399,2893 h15
  text "RB8" at 6676,2893 h15
  text "VCC" at 5405,2796 h15
  text "RB7" at 6672,2792 h15
  text "+" at 6065,2680 h60
Top Solder:
  circle w15: c5487,3284 r8
  region: 6176,2707 6105,2707 6105,2645 6176,2645
Bottom Solder:
  circle w4: c6671,2587 r32.7
  rectangle: 6117,2642 6181,2689
  text "4" at 6683,2568 h33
